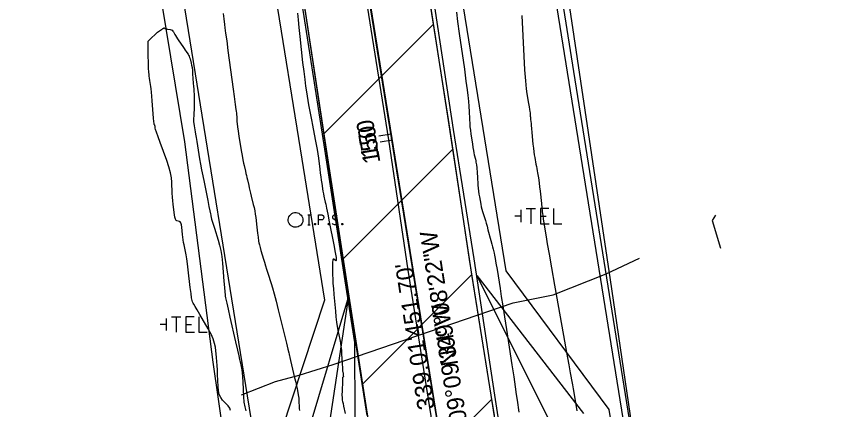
# Model space of a CAD drawing. Extents: x 2030588 to 2035216, y 462285 to 465007.
# Drawn here: x 2031163.1 to 2031296.3, y 464435 to 464499.2 of the extents above; entities that cross this region are included whole.
import ezdxf

# ---------------------------------------------------------------- set-up
doc = ezdxf.new("R2010")
doc.units = 0
for name, color, linetype in [('DT_P_Pavement_Surface', 7, 'Continuous'), ('DT_P_Slope_Break_Line', 7, 'Continuous'), ('DT_X_Contour_Minor', 7, 'Continuous'), ('GE_X_Alignment', 7, 'Continuous'), ('GE_X_Alignment_100_Bearings', 7, 'Continuous'), ('GE_X_Alignment_100_Distances', 7, 'Continuous'), ('GE_X_Alignment_100_Stations', 7, 'Continuous'), ('MD_P_CONST_LIMITS', 7, 'Continuous'), ('PV_X_COP', 7, 'Continuous'), ('PV_X_EOP', 7, 'Continuous'), ('PV_X_Shoulder_Aggregate', 7, 'Continuous'), ('RW_X_CL', 7, 'Continuous'), ('RW_X_CL_100_Bearings', 7, 'Continuous'), ('RW_X_CL_100_Distances', 7, 'Continuous'), ('RW_X_CL_100_Stations', 7, 'Continuous'), ('RW_X_Esmt_SH', 7, 'Continuous'), ('SV_P_Mon_Cells_Set', 7, 'Continuous'), ('UT_X_Cable_TV', 7, 'Continuous'), ('UT_X_Electric', 7, 'Continuous'), ('UT_X_Telecom', 7, 'Continuous'), ('UT_X_Telecom_Cells', 7, 'Continuous'), ('VG_X_Tree_Line_Lt', 7, 'Continuous')]:
    doc.layers.add(name, color=color, linetype=linetype)

msp = doc.modelspace()

# ---------------------------------------------------------------- linework, layer by layer
at = {"layer": 'DT_P_Pavement_Surface'}
for p, q in [((2031213.28, 464480.03), (2031231.21, 464497.96)), ((2031216.41, 464459.59), (2031234.35, 464477.53)), ((2031219.59, 464439.2), (2031237.45, 464457.06)), ((2031225.56, 464421.6), (2031240.71, 464436.75))]:
    msp.add_line(p, q, dxfattribs=at)
msp.add_lwpolyline([(2031241.12, 464434.08), (2031240.61, 464437.4), (2031237.49, 464456.78), (2031233.75, 464481.5), (2031229.94, 464506.21), (2031226.23, 464530.93), (2031222.43, 464555.64), (2031221.66, 464560.58), (2031201.32, 464557.3), (2031205.88, 464527.65), (2031209.79, 464502.96), (2031213.55, 464478.25), (2031217.34, 464453.54), (2031220.9, 464430.81)], dxfattribs=at)
at = {"layer": 'DT_P_Slope_Break_Line'}
for p, q in [((2031238.25, 464456.91), (2031255.66, 464434.39)), ((2031238.25, 464456.91), (2031249.98, 464433.48)), ((2031209.39, 464426.93), (2031217.34, 464453.54)), ((2031213.45, 464427.59), (2031217.34, 464453.54))]:
    msp.add_line(p, q, dxfattribs=at)
at = {"layer": 'DT_X_Contour_Minor'}
for points in [[(2031196.86, 464499.7), (2031196.92, 464499.22), (2031196.97, 464498.82), (2031197.08, 464497.86), (2031197.15, 464497.33), (2031197.26, 464496.45), (2031197.43, 464495.21), (2031197.64, 464493.62), (2031198.26, 464488.93), (2031198.47, 464487.35), (2031198.63, 464486.14), (2031198.75, 464485.29), (2031198.82, 464484.81), (2031198.95, 464484.03), (2031198.99, 464483.74), (2031199.03, 464483.44), (2031199.05, 464483.14), (2031199.07, 464482.85), (2031199.11, 464482.05), (2031199.14, 464481.68), (2031199.2, 464481.16), (2031199.3, 464480.49), (2031199.42, 464479.68), (2031199.8, 464477.31), (2031199.94, 464476.49), (2031200.06, 464475.8), (2031200.17, 464475.26), (2031200.26, 464474.85), (2031200.49, 464473.94), (2031200.58, 464473.59), (2031200.66, 464473.25), (2031200.74, 464472.9), (2031200.82, 464472.54), (2031201.03, 464471.59), (2031201.12, 464471.21), (2031201.22, 464470.8), (2031201.32, 464470.35), (2031201.45, 464469.87), (2031201.78, 464468.53), (2031201.9, 464468.02), (2031202.01, 464467.49), (2031202.1, 464466.94), (2031202.18, 464466.37), (2031202.36, 464464.83), (2031202.42, 464464.3), (2031202.48, 464463.85), (2031202.52, 464463.48), (2031202.56, 464463.19), (2031202.65, 464462.54), (2031202.7, 464462.26), (2031202.78, 464461.91), (2031202.89, 464461.49), (2031203.02, 464461), (2031203.42, 464459.61), (2031203.58, 464459.08), (2031203.75, 464458.52), (2031203.93, 464457.93), (2031204.13, 464457.32), (2031204.67, 464455.64), (2031204.9, 464454.9), (2031205.17, 464453.93), (2031205.48, 464452.74), (2031205.83, 464451.31), (2031206.84, 464447.21), (2031207.17, 464445.86), (2031207.41, 464444.89), (2031207.55, 464444.3), (2031207.61, 464444.08), (2031207.62, 464444.02), (2031207.63, 464444), (2031207.63, 464443.98), (2031207.63, 464443.97), (2031207.64, 464443.96), (2031207.64, 464443.95), (2031207.66, 464443.84), (2031207.73, 464443.54), (2031207.85, 464443.04), (2031208.02, 464442.35), (2031208.52, 464440.24), (2031208.69, 464439.51), (2031208.83, 464438.92), (2031208.93, 464438.46), (2031208.99, 464438.13), (2031209.11, 464437.43), (2031209.15, 464437.16), (2031209.19, 464436.89), (2031209.21, 464436.61), (2031209.23, 464436.32), (2031209.26, 464435.55), (2031209.28, 464435.24), (2031209.29, 464434.91)], [(2031208.98, 464499.72), (2031209.08, 464498.66), (2031209.21, 464497.39), (2031209.37, 464495.91), (2031209.83, 464491.69), (2031210, 464490.2), (2031210.16, 464488.91), (2031210.31, 464487.81), (2031210.45, 464486.92), (2031210.81, 464484.78), (2031210.96, 464483.97), (2031211.1, 464483.14), (2031211.26, 464482.3), (2031211.43, 464481.45), (2031211.88, 464479.14), (2031212.04, 464478.3), (2031212.18, 464477.51), (2031212.3, 464476.76), (2031212.39, 464476.06), (2031212.62, 464474.26), (2031212.7, 464473.61), (2031212.78, 464473.01), (2031212.86, 464472.46), (2031212.94, 464471.96), (2031213.14, 464470.69), (2031213.21, 464470.25), (2031213.27, 464469.89), (2031213.33, 464469.59), (2031213.38, 464469.38), (2031213.52, 464468.89), (2031213.59, 464468.55), (2031213.73, 464467.91), (2031213.92, 464466.95), (2031214.18, 464465.69), (2031214.92, 464461.92), (2031215.15, 464460.69), (2031215.28, 464459.85), (2031215.31, 464459.38), (2031215.24, 464459.3), (2031214.91, 464459.57), (2031214.81, 464459.59), (2031214.73, 464459.43), (2031214.69, 464459.1), (2031214.69, 464458.6), (2031214.71, 464457.03), (2031214.73, 464456.39), (2031214.77, 464455.64), (2031214.84, 464454.78), (2031214.92, 464453.82), (2031215.17, 464451.12), (2031215.26, 464450.17), (2031215.36, 464449.32), (2031215.47, 464448.59), (2031215.58, 464447.98), (2031215.89, 464446.48), (2031216, 464445.91), (2031216.08, 464445.33), (2031216.15, 464444.73), (2031216.19, 464444.12), (2031216.28, 464442.47), (2031216.31, 464441.93), (2031216.34, 464441.54), (2031216.35, 464441.3), (2031216.37, 464441.21), (2031216.39, 464441.19), (2031216.4, 464441.17), (2031216.41, 464441.12), (2031216.42, 464441.04), (2031216.43, 464440.93), (2031216.46, 464440.6), (2031216.47, 464440.49), (2031216.47, 464440.42), (2031216.46, 464440.37), (2031216.44, 464440.35), (2031216.38, 464440.34), (2031216.36, 464440.28), (2031216.34, 464440.12), (2031216.32, 464439.84), (2031216.31, 464439.45), (2031216.27, 464438.27), (2031216.26, 464437.88), (2031216.25, 464437.59), (2031216.25, 464437.39), (2031216.25, 464437.3), (2031216.26, 464437.18), (2031216.26, 464437.13), (2031216.27, 464437.07), (2031216.27, 464437), (2031216.27, 464436.92), (2031216.29, 464436.69), (2031216.3, 464436.55), (2031216.35, 464436.33), (2031216.42, 464436.02), (2031216.51, 464435.61), (2031216.79, 464434.42)], [(2031234.92, 464499.88), (2031235.13, 464498.39), (2031235.4, 464496.43), (2031236.22, 464490.6), (2031236.49, 464488.66), (2031236.69, 464487.22), (2031236.81, 464486.28), (2031236.86, 464485.84), (2031236.9, 464485.33), (2031236.92, 464485.09), (2031236.94, 464484.76), (2031236.96, 464484.34), (2031236.98, 464483.83), (2031237.05, 464482.35), (2031237.09, 464481.78), (2031237.14, 464481.2), (2031237.21, 464480.62), (2031237.29, 464480.01), (2031237.54, 464478.39), (2031237.63, 464477.82), (2031237.71, 464477.34), (2031237.78, 464476.94), (2031237.85, 464476.63), (2031238.02, 464475.91), (2031238.08, 464475.65), (2031238.12, 464475.41), (2031238.16, 464475.19), (2031238.19, 464475), (2031238.24, 464474.51), (2031238.26, 464474.28), (2031238.29, 464473.97), (2031238.32, 464473.57), (2031238.35, 464473.09), (2031238.43, 464471.69), (2031238.47, 464471.17), (2031238.52, 464470.67), (2031238.59, 464470.2), (2031238.67, 464469.74), (2031238.9, 464468.55), (2031238.99, 464468.12), (2031239.09, 464467.72), (2031239.18, 464467.37), (2031239.28, 464467.05), (2031239.54, 464466.24), (2031239.65, 464465.9), (2031239.77, 464465.47), (2031239.92, 464464.95), (2031240.08, 464464.35), (2031240.53, 464462.63), (2031240.68, 464462.05), (2031240.81, 464461.59), (2031240.9, 464461.24), (2031240.96, 464461.01), (2031241.08, 464460.55), (2031241.14, 464460.26), (2031241.24, 464459.72), (2031241.38, 464458.92), (2031241.55, 464457.88), (2031242.05, 464454.78), (2031242.25, 464453.49), (2031242.49, 464451.95), (2031242.77, 464450.16), (2031243.08, 464448.12), (2031243.96, 464442.36), (2031244.27, 464440.38), (2031244.51, 464438.76), (2031244.7, 464437.49), (2031244.84, 464436.58), (2031245.12, 464434.64)], [(2031245.58, 464499.36), (2031245.93, 464492.71), (2031246.06, 464490.46), (2031246.18, 464488.68), (2031246.29, 464487.38), (2031246.4, 464486.55), (2031246.69, 464484.98), (2031246.79, 464484.44), (2031246.86, 464484.01), (2031246.91, 464483.7), (2031246.94, 464483.49), (2031246.98, 464483.09), (2031246.99, 464482.93), (2031247.01, 464482.77), (2031247.02, 464482.61), (2031247.04, 464482.45), (2031247.08, 464482), (2031247.1, 464481.77), (2031247.14, 464481.4), (2031247.19, 464480.89), (2031247.24, 464480.26), (2031247.42, 464478.37), (2031247.49, 464477.7), (2031247.55, 464477.11), (2031247.63, 464476.6), (2031247.7, 464476.16), (2031247.89, 464475.11), (2031247.97, 464474.72), (2031248.03, 464474.36), (2031248.1, 464474.01), (2031248.16, 464473.68), (2031248.31, 464472.84), (2031248.37, 464472.46), (2031248.44, 464471.98), (2031248.51, 464471.39), (2031248.59, 464470.68), (2031248.8, 464468.65), (2031248.86, 464467.99), (2031248.91, 464467.51), (2031248.94, 464467.23), (2031248.95, 464467.13), (2031248.95, 464467.13), (2031248.95, 464467.13), (2031248.95, 464467.13), (2031248.95, 464467.13), (2031248.95, 464467.13), (2031248.95, 464467.12), (2031248.97, 464467.02), (2031249.02, 464466.71), (2031249.1, 464466.18), (2031249.22, 464465.45), (2031249.56, 464463.22), (2031249.75, 464462.11), (2031250.04, 464460.42), (2031250.43, 464458.17), (2031250.93, 464455.36), (2031252.4, 464447.11), (2031252.89, 464444.37), (2031253.25, 464442.36), (2031253.49, 464441.06), (2031253.6, 464440.49), (2031253.72, 464439.92), (2031253.78, 464439.61), (2031253.88, 464439.1), (2031254, 464438.4), (2031254.15, 464437.5), (2031254.59, 464434.84)], [(2031184.64, 464494), (2031184.63, 464494.5), (2031184.63, 464494.86), (2031184.63, 464495.08), (2031184.64, 464495.17), (2031184.65, 464495.2), (2031184.65, 464495.21), (2031184.66, 464495.22), (2031184.67, 464495.23), (2031184.68, 464495.24), (2031184.7, 464495.27), (2031184.74, 464495.3), (2031184.83, 464495.38), (2031184.97, 464495.52), (2031185.16, 464495.7), (2031185.74, 464496.26), (2031185.95, 464496.46), (2031186.13, 464496.62), (2031186.3, 464496.75), (2031186.44, 464496.85), (2031186.78, 464497.06), (2031186.89, 464497.13), (2031186.98, 464497.19), (2031187.04, 464497.23), (2031187.08, 464497.26), (2031187.15, 464497.31), (2031187.18, 464497.33), (2031187.21, 464497.33), (2031187.24, 464497.33), (2031187.27, 464497.31), (2031187.35, 464497.25), (2031187.39, 464497.22), (2031187.48, 464497.2), (2031187.6, 464497.17), (2031187.75, 464497.14), (2031188.21, 464497.06), (2031188.37, 464497.02), (2031188.52, 464496.94), (2031188.64, 464496.82), (2031188.73, 464496.68), (2031188.97, 464496.25), (2031189.08, 464496.07), (2031189.22, 464495.83), (2031189.41, 464495.55), (2031189.63, 464495.22), (2031190.28, 464494.28), (2031190.5, 464493.96), (2031190.68, 464493.7), (2031190.82, 464493.49), (2031190.92, 464493.34), (2031191.14, 464493.03), (2031191.22, 464492.89), (2031191.3, 464492.72), (2031191.38, 464492.51), (2031191.45, 464492.26), (2031191.64, 464491.55), (2031191.71, 464491.25), (2031191.77, 464490.87), (2031191.83, 464490.4), (2031191.87, 464489.86), (2031191.98, 464488.31), (2031192.02, 464487.79), (2031192.05, 464487.38), (2031192.07, 464487.09), (2031192.08, 464486.91), (2031192.1, 464486.59), (2031192.11, 464486.43), (2031192.11, 464486.19), (2031192.11, 464485.87), (2031192.11, 464485.47), (2031192.1, 464484.31), (2031192.1, 464483.9), (2031192.09, 464483.55), (2031192.08, 464483.26), (2031192.07, 464483.03), (2031192.03, 464482.5), (2031192.02, 464482.28), (2031192.04, 464482.02), (2031192.07, 464481.71), (2031192.12, 464481.37), (2031192.29, 464480.39), (2031192.36, 464479.97), (2031192.45, 464479.44), (2031192.55, 464478.81), (2031192.68, 464478.06), (2031193.02, 464475.94), (2031193.16, 464475.11), (2031193.32, 464474.19), (2031193.52, 464473.2), (2031193.73, 464472.13), (2031194.34, 464469.17), (2031194.54, 464468.18), (2031194.69, 464467.46), (2031194.78, 464467), (2031194.83, 464466.79), (2031194.87, 464466.58), (2031194.88, 464466.5), (2031194.89, 464466.44), (2031194.9, 464466.38), (2031194.91, 464466.33), (2031194.94, 464466.22), (2031194.97, 464466.09), (2031195.07, 464465.79), (2031195.22, 464465.31), (2031195.43, 464464.65), (2031196.06, 464462.67), (2031196.28, 464461.88), (2031196.47, 464461), (2031196.62, 464460.02), (2031196.73, 464458.95), (2031196.99, 464455.97), (2031197.08, 464454.98), (2031197.15, 464454.25), (2031197.19, 464453.77), (2031197.21, 464453.55), (2031197.24, 464453.3), (2031197.3, 464453.04), (2031197.43, 464452.41), (2031197.65, 464451.44), (2031197.96, 464450.1), (2031198.88, 464446.08), (2031199.18, 464444.76), (2031199.4, 464443.8), (2031199.54, 464443.21), (2031199.59, 464442.98), (2031199.62, 464442.87), (2031199.64, 464442.8), (2031199.66, 464442.7), (2031199.7, 464442.55), (2031199.74, 464442.36), (2031199.86, 464441.81), (2031199.91, 464441.51), (2031199.96, 464441.04), (2031200, 464440.39), (2031200.05, 464439.57), (2031200.18, 464437.13), (2031200.25, 464436.26), (2031200.38, 464435.49), (2031200.55, 464434.81)], [(2031198.05, 464434.88), (2031197.93, 464435.27), (2031197.66, 464435.64), (2031196.75, 464436.59), (2031196.45, 464437), (2031196.23, 464437.5), (2031196.08, 464438.1), (2031196.02, 464438.8), (2031195.95, 464440.79), (2031195.91, 464441.52), (2031195.87, 464442.22), (2031195.82, 464442.89), (2031195.76, 464443.53), (2031195.58, 464445.2), (2031195.46, 464445.85), (2031195.22, 464446.57), (2031194.88, 464447.35), (2031194.43, 464448.2), (2031193.07, 464450.53), (2031192.62, 464451.31), (2031192.29, 464451.88), (2031192.07, 464452.26), (2031191.97, 464452.43), (2031191.84, 464452.62), (2031191.79, 464452.82), (2031191.71, 464453.27), (2031191.61, 464453.98), (2031191.49, 464454.94), (2031191.16, 464457.83), (2031191.03, 464458.83), (2031190.92, 464459.66), (2031190.81, 464460.32), (2031190.72, 464460.82), (2031190.48, 464461.91), (2031190.39, 464462.33), (2031190.32, 464462.75), (2031190.26, 464463.18), (2031190.21, 464463.63), (2031190.09, 464464.82), (2031190.03, 464465.21), (2031189.95, 464465.5), (2031189.85, 464465.68), (2031189.71, 464465.76), (2031189.32, 464465.84), (2031189.19, 464465.92), (2031189.07, 464466.11), (2031188.97, 464466.42), (2031188.9, 464466.83), (2031188.73, 464468.08), (2031188.67, 464468.57), (2031188.62, 464469.12), (2031188.58, 464469.71), (2031188.55, 464470.36), (2031188.49, 464472.14), (2031188.42, 464472.86), (2031188.26, 464473.69), (2031188, 464474.63), (2031187.65, 464475.67), (2031186.58, 464478.6), (2031186.23, 464479.57), (2031185.98, 464480.29), (2031185.82, 464480.76), (2031185.77, 464480.97), (2031185.75, 464481.2), (2031185.74, 464481.28), (2031185.73, 464481.35), (2031185.71, 464481.42), (2031185.68, 464481.47), (2031185.61, 464481.59), (2031185.58, 464481.73), (2031185.54, 464482.06), (2031185.49, 464482.58), (2031185.44, 464483.29), (2031185.28, 464485.44), (2031185.22, 464486.19), (2031185.16, 464486.83), (2031185.11, 464487.36), (2031185.05, 464487.78), (2031184.9, 464488.76), (2031184.85, 464489.12), (2031184.8, 464489.45), (2031184.77, 464489.76), (2031184.75, 464490.05), (2031184.69, 464490.79), (2031184.67, 464491.1), (2031184.66, 464491.49), (2031184.65, 464491.95), (2031184.64, 464492.48), (2031184.64, 464494)], [(2031277.2, 464466.78), (2031276.68, 464465.89), (2031278.03, 464461.4)]]:
    msp.add_lwpolyline(points, dxfattribs=at)
at = {"layer": 'GE_X_Alignment'}
msp.add_line((2031257.42, 464274.28), (2031203.46, 464608.93), dxfattribs=at)
at = {"layer": 'GE_X_Alignment_100_Stations'}
msp.add_line((2031224.25, 464479.97), (2031222.28, 464479.65), dxfattribs=at)
at = {"layer": 'MD_P_CONST_LIMITS'}
for points in [[(2031195.12, 464566.43), (2031197.51, 464551.62), (2031201.49, 464526.94), (2031205.46, 464502.26), (2031209.44, 464477.58), (2031213.42, 464452.9), (2031204.57, 464426.16)], [(2031335.72, 464342.73), (2031348.07, 464341.16), (2031359.8, 464346.82), (2031370.03, 464354.45), (2031376.83, 464361.46), (2031382.87, 464378.84), (2031377.1, 464386.74), (2031358.08, 464381.31), (2031336.1, 464372.31), (2031297.64, 464356), (2031288.95, 464369.08), (2031270.23, 464370.68), (2031259.85, 464435.07), (2031243.04, 464457.68), (2031227.12, 464556.39)]]:
    msp.add_lwpolyline(points, dxfattribs=at)
at = {"layer": 'PV_X_COP'}
msp.add_lwpolyline([(2031239.82, 464378.92), (2031237.29, 464394.23), (2031234, 464414.13), (2031230.52, 464435.72), (2031227.06, 464457.78), (2031223.87, 464479.05), (2031220.41, 464500.85), (2031217.21, 464522.28), (2031213.78, 464544.16), (2031210.25, 464566.43), (2031206.68, 464588.5), (2031203.46, 464608.93)], dxfattribs=at)
at = {"layer": 'PV_X_EOP'}
for points in [[(2031251.66, 464369.87), (2031250.51, 464376.28), (2031247.25, 464396.03), (2031243.95, 464415.75), (2031240.61, 464437.4), (2031237.04, 464459.53), (2031233.89, 464480.65), (2031230.49, 464502.51), (2031227.3, 464523.94), (2031223.95, 464545.8), (2031220.51, 464568.02), (2031216.93, 464590.23), (2031213.72, 464610.74)], [(2031220.38, 464434.08), (2031216.94, 464456.07), (2031213.65, 464477.62), (2031210.38, 464499.25), (2031206.93, 464520.75), (2031203.59, 464542.74), (2031200.18, 464564.75), (2031196.7, 464586.93), (2031193.38, 464607.22)]]:
    msp.add_lwpolyline(points, dxfattribs=at)
at = {"layer": 'PV_X_Shoulder_Aggregate'}
for points in [[(2031244.49, 464415.82), (2031241.2, 464437.39), (2031237.84, 464459.63), (2031234.47, 464480.77), (2031231.11, 464502.61), (2031227.92, 464524.01), (2031224.49, 464545.89), (2031220.99, 464568.08), (2031217.44, 464590.34), (2031214.14, 464610.7)], [(2031218.4, 464433.79), (2031218.36, 464445.96), (2031216.75, 464456.06), (2031213.47, 464477.52), (2031210.09, 464499.18), (2031206.66, 464520.67), (2031203.21, 464542.69), (2031199.69, 464564.68), (2031196.27, 464586.9), (2031193.02, 464607.09)]]:
    msp.add_lwpolyline(points, dxfattribs=at)
at = {"layer": 'RW_X_CL'}
msp.add_line((2031264.45, 464230.53), (2031192.71, 464676.45), dxfattribs=at)
at = {"layer": 'RW_X_CL_100_Stations'}
msp.add_line((2031224.48, 464479.01), (2031222.5, 464478.69), dxfattribs=at)
at = {"layer": 'RW_X_Esmt_SH'}
for p, q in [((2031294.07, 464235.3), (2031222.33, 464681.22)), ((2031234.84, 464225.77), (2031163.1, 464671.69))]:
    msp.add_line(p, q, dxfattribs=at)
at = {"layer": 'SV_P_Mon_Cells_Set'}
for p, q in [((2031210.7, 464466.8), (2031211.05, 464466.8)), ((2031210.87, 464465.2), (2031210.87, 464466.8)), ((2031210.7, 464465.2), (2031211.05, 464465.2))]:
    msp.add_line(p, q, dxfattribs=at)
for points in [[(2031212.44, 464465.2), (2031212.44, 464466.8), (2031212.97, 464466.8), (2031213.02, 464466.78), (2031213.1, 464466.76), (2031213.13, 464466.73), (2031213.17, 464466.71), (2031213.21, 464466.65), (2031213.24, 464466.58), (2031213.27, 464466.48), (2031213.27, 464466.33), (2031213.25, 464466.28), (2031213.23, 464466.2), (2031213.19, 464466.12), (2031213.14, 464466.08), (2031213.11, 464466.05), (2031213.06, 464466.03), (2031212.97, 464466.02), (2031212.44, 464466.02)], [(2031215.45, 464466.68), (2031215.43, 464466.71), (2031215.39, 464466.73), (2031215.29, 464466.77), (2031215.17, 464466.8), (2031215.08, 464466.8), (2031215.05, 464466.8), (2031214.91, 464466.76), (2031214.79, 464466.68), (2031214.71, 464466.58), (2031214.69, 464466.48), (2031214.69, 464466.41), (2031214.71, 464466.3), (2031214.8, 464466.22), (2031215.4, 464465.84), (2031215.46, 464465.79), (2031215.48, 464465.74), (2031215.5, 464465.66), (2031215.5, 464465.59), (2031215.49, 464465.51), (2031215.48, 464465.46), (2031215.46, 464465.4), (2031215.44, 464465.35), (2031215.41, 464465.31), (2031215.38, 464465.27), (2031215.35, 464465.25), (2031215.3, 464465.22), (2031215.27, 464465.21), (2031215.17, 464465.2), (2031215.02, 464465.2), (2031214.92, 464465.22), (2031214.78, 464465.31), (2031214.69, 464465.39)], [(2031211.83, 464465.41), (2031211.89, 464465.41), (2031211.92, 464465.39), (2031211.95, 464465.34), (2031211.95, 464465.27), (2031211.92, 464465.22), (2031211.89, 464465.2), (2031211.83, 464465.2), (2031211.8, 464465.22), (2031211.77, 464465.27), (2031211.77, 464465.34), (2031211.8, 464465.39), (2031211.83, 464465.41)], [(2031214.08, 464465.41), (2031214.14, 464465.41), (2031214.17, 464465.39), (2031214.2, 464465.34), (2031214.2, 464465.27), (2031214.17, 464465.22), (2031214.14, 464465.2), (2031214.08, 464465.2), (2031214.05, 464465.22), (2031214.01, 464465.27), (2031214.01, 464465.34), (2031214.05, 464465.39), (2031214.08, 464465.41)], [(2031216.26, 464465.41), (2031216.32, 464465.41), (2031216.35, 464465.39), (2031216.38, 464465.34), (2031216.38, 464465.27), (2031216.35, 464465.22), (2031216.32, 464465.2), (2031216.26, 464465.2), (2031216.23, 464465.22), (2031216.2, 464465.27), (2031216.2, 464465.34), (2031216.23, 464465.39), (2031216.26, 464465.41)]]:
    msp.add_lwpolyline(points, dxfattribs=at)
msp.add_ellipse((2031208.68, 464465.99), major_axis=(-0.801, 0.893), ratio=0.999987, dxfattribs=at)
at = {"layer": 'UT_X_Cable_TV'}
msp.add_lwpolyline([(2031238.8, 464585.93), (2031247.13, 464533.78), (2031254.05, 464490.2), (2031262.25, 464438.84), (2031269.7, 464392.26), (2031276.53, 464349.48), (2031283.45, 464306.23), (2031289.88, 464266.16)], dxfattribs=at)
at = {"layer": 'UT_X_Electric'}
msp.add_lwpolyline([(2031221.84, 464713.47), (2031231.94, 464645.28), (2031244.28, 464562.24), (2031252.85, 464504.34), (2031260, 464456.22), (2031264.87, 464423.29), (2031269.31, 464393.31), (2031274.04, 464361.48), (2031280.97, 464314.78), (2031288.22, 464265.92), (2031292.23, 464240.82), (2031300.29, 464190.3), (2031337.85, 463955.94)], dxfattribs=at)
at = {"layer": 'UT_X_Telecom'}
msp.add_lwpolyline([(2031199.86, 464437.45), (2031205.42, 464439.62), (2031209.25, 464440.67), (2031214.83, 464442.4), (2031244.19, 464452.47), (2031250.71, 464453.76), (2031259.36, 464457.19), (2031264.81, 464459.73)], dxfattribs=at)
at = {"layer": 'UT_X_Telecom_Cells'}
for p, q in [((2031246.29, 464467.86), (2031247.85, 464467.86)), ((2031247.08, 464467.86), (2031247.08, 464465.36)), ((2031245.47, 464466.62), (2031244.48, 464466.62)), ((2031245.47, 464465.62), (2031245.47, 464467.62)), ((2031248.63, 464466.62), (2031249.6, 464466.62)), ((2031187.59, 464447.93), (2031187.59, 464449.93)), ((2031188.41, 464450.17), (2031189.96, 464450.17)), ((2031189.19, 464450.17), (2031189.19, 464447.67)), ((2031187.59, 464448.93), (2031186.59, 464448.93)), ((2031190.75, 464448.93), (2031191.71, 464448.93))]:
    msp.add_line(p, q, dxfattribs=at)
for points in [[(2031249.99, 464467.86), (2031248.63, 464467.86), (2031248.63, 464465.36), (2031250.09, 464465.36)], [(2031250.78, 464467.86), (2031250.78, 464465.36), (2031252.14, 464465.36)], [(2031192.11, 464450.17), (2031190.75, 464450.17), (2031190.75, 464447.67), (2031192.2, 464447.67)], [(2031192.89, 464450.17), (2031192.89, 464447.67), (2031194.25, 464447.67)]]:
    msp.add_lwpolyline(points, dxfattribs=at)
at = {"layer": 'VG_X_Tree_Line_Lt'}
msp.add_lwpolyline([(2031171.25, 464603.92), (2031180.58, 464539.24), (2031190.57, 464478.71), (2031195.18, 464442.8), (2031200.67, 464404.62), (2031207.96, 464347.78), (2031213.54, 464319.45), (2031224.29, 464260.06), (2031224.63, 464250.71), (2031227.58, 464205.15)], dxfattribs=at)

# ---------------------------------------------------------------- texts
at = {"layer": 'GE_X_Alignment_100_Bearings'}
msp.add_text('N09°09\'34"W', height=2.7997, rotation=99.1593, dxfattribs=at).set_placement((2031237.09, 464430.49))
at = {"layer": 'GE_X_Alignment_100_Distances'}
msp.add_text("339.01'", height=2.8, rotation=99.1593, dxfattribs=at).set_placement((2031231.43, 464435.24))
at = {"layer": 'GE_X_Alignment_100_Stations'}
msp.add_text('150', height=2.8, rotation=99.1593, dxfattribs=at).set_placement((2031222.3, 464476.35))
at = {"layer": 'RW_X_CL_100_Bearings'}
msp.add_text('N09°08\'22"W', height=2.7997, rotation=99.1395, dxfattribs=at).set_placement((2031235.23, 464442.38))
at = {"layer": 'RW_X_CL_100_Distances'}
msp.add_text("451.70'", height=2.8, rotation=99.1395, dxfattribs=at).set_placement((2031229.57, 464447.13))
at = {"layer": 'RW_X_CL_100_Stations'}
msp.add_text('150', height=2.8, rotation=99.1395, dxfattribs=at).set_placement((2031222.53, 464475.39))

doc.saveas('drawing.dxf')
